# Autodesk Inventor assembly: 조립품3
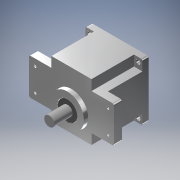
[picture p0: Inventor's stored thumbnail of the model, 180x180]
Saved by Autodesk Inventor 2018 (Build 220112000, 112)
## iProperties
Created: 2020-07
Part Number: 조립품3
Material: 일반
Document SubType Name: Assembly
Designer: Admin
Author: Admin
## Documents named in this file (10)
- C:\Users\Admin\Desktop\700707V1009\조립품.iam
- C:\Users\Admin\Desktop\700707V1009\본체.ipt
- C:\Users\Admin\Desktop\700707V1009\커버.ipt
- C:\Users\Admin\Desktop\700707V1009\메인 축.ipt
- C:\Users\Admin\Desktop\700707V1009\베어링 608.ipt
- C:\Users\Admin\Desktop\700707V1009\서브 축.ipt
- C:\Users\Admin\Desktop\700707V1009\베어링 6003.ipt
- C:\Users\Admin\Desktop\700707V1009\볼트 M4.ipt
- C:\Users\Admin\Desktop\700707V1009\오일 실 17 32 8.ipt
- C:\Users\Admin\Desktop\700707V1009\오일 실 8 22 7.ipt
